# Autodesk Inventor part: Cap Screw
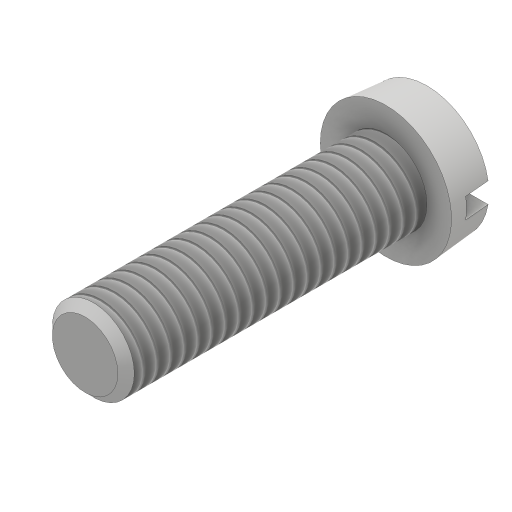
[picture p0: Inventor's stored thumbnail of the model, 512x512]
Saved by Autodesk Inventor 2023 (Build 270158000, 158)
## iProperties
Created: 2016-05
Part Number: Cap Screw
Material: Generic
Document SubType Name: Modeling
Designer: CADCIM
Density: 1 g/cm^3
Appearance: Default
Author: CADCIM
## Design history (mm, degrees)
sketch "Sketch2"
  geometry: C1 r 4.8 at (0, 0); 1 further point
  constraints: 1 centre point, 1 coincident
  dimensions: "d0" = 9.6 diameter of C1
extrude "Extrusion1" new body sketch "Sketch2" distance "d1" = 3; taper "d2" = -5 deg
sketch "Sketch3"
  geometry: C1 r 3 at (0, 0); 1 further point
  constraints: 1 centre point, 1 coincident
  dimensions: "d3" = 6 diameter of C1
extrude "Extrusion2" join sketch "Sketch3" distance "d4" = 22; taper "d5" = 0 deg
sketch "Sketch4"
  geometry: L1 (-13.358, -0.75)-(13.048, -0.75); L2 (13.048, -0.75)-(13.048, 0.75); L3 (13.048, 0.75)-(-13.358, 0.75); L4 (-13.358, 0.75)-(-13.358, -0.75); L5 (0, 0)-(-15.613, 0)
  constraints: 10 end point, 3 parallel, 1 horizontal, 1 perpendicular, 1 other
  dimensions: "d6" = 1.5 distance of L3.end L1.start
extrude "Extrusion3" cut sketch "Sketch4" distance "d7" = 1.8; taper "d8" = 0 deg
thread "Thread1" dims "d9" = 10, "d10" = 0
chamfer "Chamfer1" distance "d11" = 0.6; stored, may be unused: second distance "d12" = 2, angle "d13" = 45 deg
body "Solid1"
